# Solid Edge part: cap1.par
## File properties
Author: Sarvanan
Template: sync iso part.par
Last saved by: Sarvanan
Revision: 37
Application: Solid Edge
Accuracy: 0.990
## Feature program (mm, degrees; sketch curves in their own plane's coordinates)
sketch for "Hole_5" plane through (53.6271, 124.6139, 55.8947) normal (-0.003821, 0, 0.999993) x-axis (0, -1, 0)
hole "Hole_5" diameter 6 through  CounterBoreDepth = 16 mm; VBottomAngle = 118 deg
pattern "unnamed Pattern 1" of "Hole_5"
sketch for "unnamed Hole 1" plane through (17.8193, 125.4751, 43.9627) normal (0.018369, 0, 0.999831) x-axis (0, 1, 0)
hole "unnamed Hole 1" through
sketch for "Hole_3" plane through (89.4367, 125.4751, 43.304) normal (0, 0, 1) x-axis (0, 1, 0)
hole "Hole_3" diameter 12 through
pattern "unnamed Pattern 2" of "Hole_3", "unnamed Hole 1"
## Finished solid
Body 1: solid body, 40 faces, 101 edges, 62 vertices, 2 separate solids.
  Faces by surface: plane 24, cylinder 16
  Edges by curve: line 69, circle 25, intersection 5, ellipse 2
Bounding box of the edges (mm): 108.015 x 166.185 x 40.589, from (-0.6107, -18, 15.304) to (107.4045, 148.185, 55.8933).
Cylindrical faces by radius (mm): R3 x1, R4 x1, R6 x2, R17 x3, R21.4995 x1, R24 x1, R48 x2, R54 x5
Planar faces by outward normal: +x 3, +y 2, +z 4, -x 4, -y 2, -z 6, oblique 3
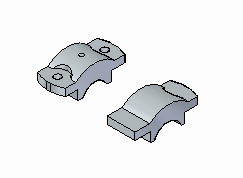
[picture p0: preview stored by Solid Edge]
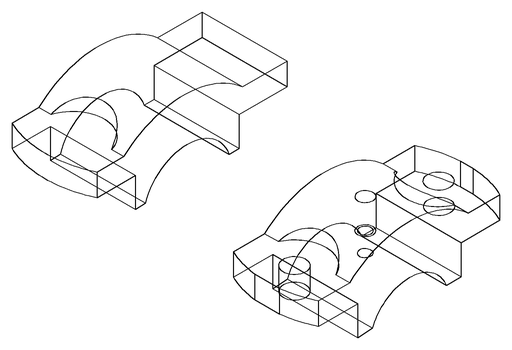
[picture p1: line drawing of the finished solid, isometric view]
